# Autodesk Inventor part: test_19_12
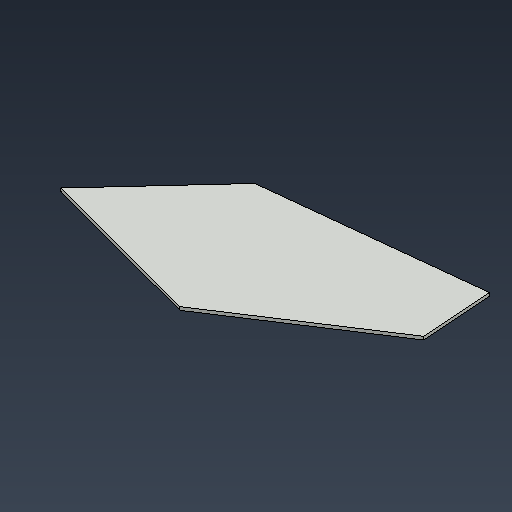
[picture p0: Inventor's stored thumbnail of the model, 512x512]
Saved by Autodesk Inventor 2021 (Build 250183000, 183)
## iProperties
Manager: =<Keywords> <Authority> <Part number>
Created: 2019-12
Part Number: test_19_12
Project: projekt
Material: S355
Description: polotovar
Document SubType Name: Sheet Metal
Designer: naus
Authority: cislo projektu
Stock Number: norma
Density: 7.8 g/cm^3
Sheet Metal Rule: Default_mm
Appearance: RAL7038
Mass: 3.03349 g
Surface Area: 16.1557 cm^2
Volume: 0.388909 cm^3
SM_Thickness: 0,5
SM_Length: 0
SM_Width: 0
SM_Extents: 0x0
Volume_Fluid_Category: NO
Title: nazov
Subject: material
Author: naus
Keywords: 27
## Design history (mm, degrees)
node "Face1"
  sketch "Sketch1"
    geometry: L1 (-11.576, 7.593)-(-26.148, -8.219); L2 (-26.148, -8.219)-(-0.725, -14.976); L3 (-0.725, -14.976)-(22.363, 0.077); L4 (22.363, 0.077)-(21.606, 11.169); L5 (21.606, 11.169)-(-11.576, 7.593); 1 further point
    constraints: 10 end point
body "Solid1"
face "Plate1" dims "d0" = 0.5 (= Thickness)
other parameters: "Pipe_Thickness_tl" = 5 [user parameter], "Thickness" = 0.5 (derived), "KFactor" = 4.4, "BendRadius" = 0.5 (= Thickness), "BendReliefWidth" = 0.5 (= Thickness), "BendReliefDepth" = 0.25 (= 0.5 x Thickness), "CornerReliefSize" = 2 (= 4 x Thickness), "SeamGap" = 0.01, "MinimumRemnant" = 1 (= 2 x Thickness), "TransitionRadius" = 0.5 (= BendRadius), "JacobiRadiusSize" = 0.5 (= BendRadius), "GapSize" = 0.5 (= Thickness)
